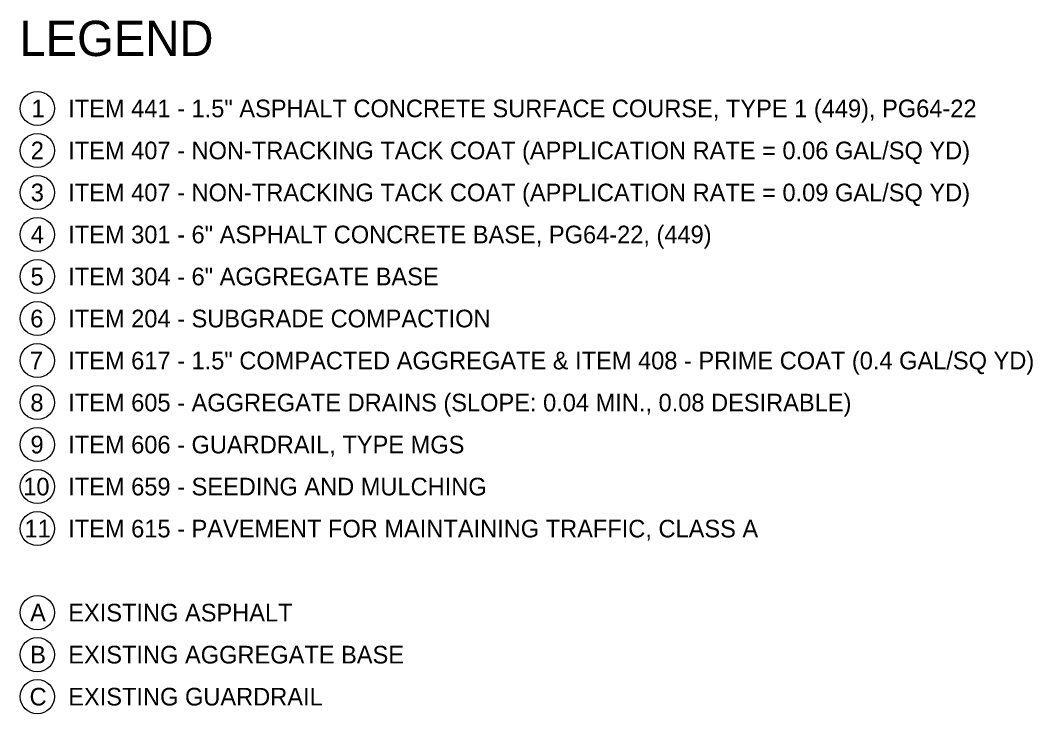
# Model space of a CAD drawing. Extents: x -396 to 156, y -166 to 172.
# Drawn here: x 131.49 to 155.58, y -138.05 to -121.54 of the extents above; entities that cross this region are included whole.
import ezdxf

# ---------------------------------------------------------------- set-up
doc = ezdxf.new("R2010")
doc.units = 0
doc.layers.add('SH_Text', color=7, linetype='Continuous')
doc.layers.add('TX_P_1', color=7, linetype='Continuous')

msp = doc.modelspace()

# ---------------------------------------------------------------- linework, layer by layer
at = {"layer": 'TX_P_1'}
for centre in [(131.9, -123.644), (131.9, -124.644), (131.9, -125.644), (131.9, -126.644), (131.9, -127.644), (131.9, -128.644), (131.9, -129.644), (131.9, -130.644), (131.9, -131.644), (131.9, -132.644), (131.9, -133.644), (131.9, -135.644), (131.9, -136.644), (131.9, -137.644)]:
    msp.add_circle(centre, 0.406, dxfattribs=at)

# ---------------------------------------------------------------- texts
at = {"layer": 'SH_Text'}
msp.add_text('LEGEND', height=0.84, dxfattribs=at).set_placement((131.471, -122.397))
at = {"layer": 'TX_P_1'}
for s, p in [('1', (131.762, -123.854)), ('ITEM 441 - 1.5" ASPHALT CONCRETE SURFACE COURSE, TYPE 1 (449), PG64-22', (132.635, -123.854)), ('2', (131.743, -124.854)), ('ITEM 407 - NON-TRACKING TACK COAT (APPLICATION RATE = 0.06 GAL/SQ YD)', (132.635, -124.854)), ('3', (131.744, -125.854)), ('ITEM 407 - NON-TRACKING TACK COAT (APPLICATION RATE = 0.09 GAL/SQ YD)', (132.635, -125.854)), ('4', (131.744, -126.854)), ('ITEM 301 - 6" ASPHALT CONCRETE BASE, PG64-22, (449)', (132.635, -126.854)), ('5', (131.739, -127.854)), ('ITEM 304 - 6" AGGREGATE BASE', (132.635, -127.854)), ('6', (131.731, -128.854)), ('ITEM 204 - SUBGRADE COMPACTION', (132.635, -128.854)), ('7', (131.723, -129.854)), ('ITEM 617 - 1.5" COMPACTED AGGREGATE & ITEM 408 - PRIME COAT (0.4 GAL/SQ YD)', (132.635, -129.854)), ('8', (131.735, -130.854)), ('ITEM 605 - AGGREGATE DRAINS (SLOPE: 0.04 MIN., 0.08 DESIRABLE)', (132.635, -130.854)), ('9', (131.737, -131.854)), ('ITEM 606 - GUARDRAIL, TYPE MGS', (132.635, -131.854)), ('10', (131.565, -132.854)), ('ITEM 659 - SEEDING AND MULCHING', (132.635, -132.854)), ('11', (131.595, -133.854)), ('ITEM 615 - PAVEMENT FOR MAINTAINING TRAFFIC, CLASS A', (132.635, -133.854)), ('A', (131.728, -135.854)), ('EXISTING ASPHALT', (132.635, -135.854)), ('B', (131.73, -136.854)), ('EXISTING AGGREGATE BASE', (132.635, -136.854)), ('C', (131.715, -137.854)), ('EXISTING GUARDRAIL', (132.635, -137.854))]:
    msp.add_text(s, height=0.42, dxfattribs=at).set_placement(p)

doc.saveas('drawing.dxf')
